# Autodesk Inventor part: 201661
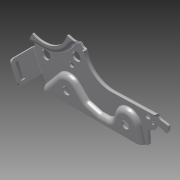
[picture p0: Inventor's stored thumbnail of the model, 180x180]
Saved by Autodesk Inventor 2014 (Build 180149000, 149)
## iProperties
Created: 2007-12
Part Number: 201661
Document SubType Name: Modeling
Designer: MM
Density: 7.85 g/cm^3
Mass: 262.658 g
Surface Area: 247.482 cm^2
Volume: 33.4596 cm^3
Description: BACK SUPPORT PLATE
Material: Steel
Appearance: Steel
Component Category: Lower Component
Author: MM
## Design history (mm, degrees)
node "200688" dims "d0" = 10
  workaxis "Work Axis1"
body "Solid1"
tag "TaggingFeature2"
workplane "Work Plane2"
feature "DerivedBody::D-200688" dims "d0" = 10
